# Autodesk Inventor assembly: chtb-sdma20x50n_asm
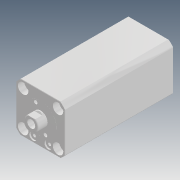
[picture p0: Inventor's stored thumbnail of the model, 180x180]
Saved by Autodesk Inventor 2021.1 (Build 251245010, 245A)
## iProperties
Created: 2018-05
Part Number: chtb-sdma20x50n_asm
Description: STEP AP214
Document SubType Name: Assembly
Designer: user
Title: chtb-sdma20x50n_asm.STEP
Revision Number: ÈÎºÎ
Sending System: SolidWorks 2016
Preprocessor: SwSTEP 2.0
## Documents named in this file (5)
- D:\Vault_2016\Projekty\Clamptek\Hydraulic\CHTB\CHTB-20\Inventor\CHTB-SDMA20x50N\chtb-sdma20x50n_asm.iam
- D:\Vault_2016\Projekty\Clamptek\Hydraulic\CHTB\CHTB-20\Inventor\CHTB-SDMA20x50N\CHTB-SDMA20X50NBT.ipt
- D:\Vault_2016\Projekty\Clamptek\Hydraulic\CHTB\CHTB-20\Inventor\CHTB-SDMA20x50N\CHTB-SDMA20X50NHSG.ipt
- D:\Vault_2016\Projekty\Clamptek\Hydraulic\CHTB\CHTB-20\Inventor\CHTB-SDMA20x50N\QG_3.ipt
- D:\Vault_2016\Projekty\Clamptek\Hydraulic\CHTB\CHTB-20\Inventor\CHTB-SDMA20x50N\socket set screw flat point_iso_ISO 4026 - M5 x 5-N.ipt
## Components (5 placed, 5 different names)
1. CHTB-SDMA20X50NBT_1
2. CHTB-SDMA20X50NHSG_2
3. QG_3_3
4. socket set screw flat point_iso_ISO 4026 - M5 x 5-N_4
5. socket set screw flat point_iso_ISO 4026 - M5 x 5-N_5
